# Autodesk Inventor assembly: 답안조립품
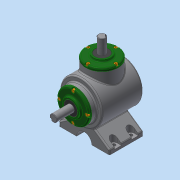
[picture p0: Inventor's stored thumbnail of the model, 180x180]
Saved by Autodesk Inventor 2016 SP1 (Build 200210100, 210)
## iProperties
Created: 2017-04
Part Number: 답안조립품
Material: 일반
Document SubType Name: Assembly
Designer: CAMTIC
Author: CAMTIC
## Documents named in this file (14)
- C:\Users\CAMTIC\Desktop\470407V1032\답안조립품.iam
- C:\Users\CAMTIC\Desktop\470407V1032\본체.ipt
- C:\Users\CAMTIC\Desktop\470407V1032\메인 베벨기어.ipt
- C:\Users\CAMTIC\Desktop\470407V1032\메인 축.ipt
- 메인 축.ipt
- C:\Users\CAMTIC\Desktop\470407V1032\베어링 6203.ipt
- C:\Users\CAMTIC\Desktop\470407V1032\볼트 M4.ipt
- C:\Users\CAMTIC\Desktop\470407V1032\서브 베벨기어.ipt
- C:\Users\CAMTIC\Desktop\470407V1032\서브 축.ipt
- 서브 축.ipt
- C:\Users\CAMTIC\Desktop\470407V1032\오일실 17 32 8.ipt
- C:\Users\CAMTIC\Desktop\470407V1032\커버.ipt
- C:\Users\CAMTIC\Desktop\470407V1032\키 4x4.ipt
- C:\Users\CAMTIC\Desktop\470407V1032\키 5x5.ipt
